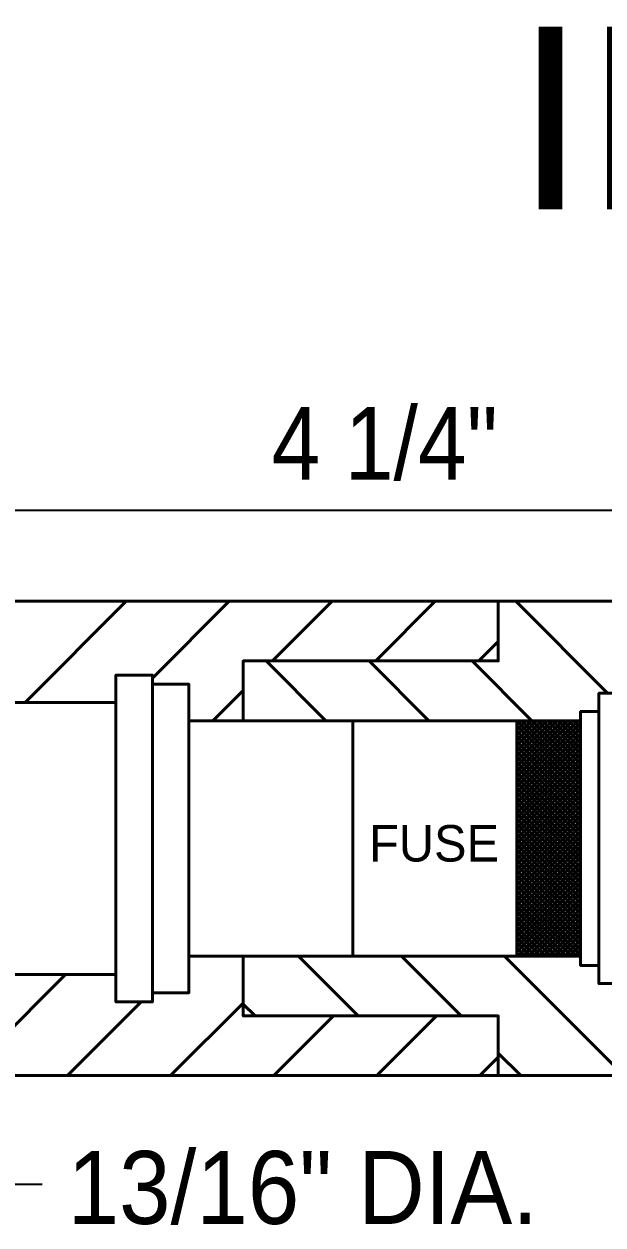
# Model space of a CAD drawing. Extents: x -1 to 679, y 0 to 440.
# Drawn here: x 505.14 to 521.03, y 230.48 to 263.39 of the extents above; entities that cross this region are included whole.
import ezdxf
from ezdxf.enums import TextEntityAlignment as Align

# ---------------------------------------------------------------- set-up
doc = ezdxf.new("R2010")
doc.units = 0
doc.header["$LTSCALE"] = 0.8
doc.layers.add('1', color=7, linetype='Continuous', lineweight=53)

msp = doc.modelspace()

# ---------------------------------------------------------------- linework, layer by layer
at = {"layer": '1', "lineweight": 35}
for p, q in [((484.1543, 250.0712), (546.1543, 250.0712)), ((504.6435, 231.5923), (505.6424, 231.5923))]:
    msp.add_line(p, q, dxfattribs=at)
at = {"layer": '1'}
for p, q in [((505.1687, 244.7994), (507.9405, 247.5712)), ((508.6637, 245.4659), (510.769, 247.5712)), ((511.9615, 245.9353), (513.5974, 247.5712)), ((514.7899, 245.9353), (516.4258, 247.5712)), ((521.1549, 245.0494), (518.6331, 247.5712)), ((517.6183, 245.9353), (518.1543, 246.4713)), ((513.4196, 244.2994), (511.7837, 245.9353)), ((516.248, 244.2994), (514.6121, 245.9353)), ((519.0764, 244.2994), (517.4405, 245.9353)), ((508.6637, 245.2994), (508.6637, 236.8431)), ((510.3256, 244.2994), (511.1543, 245.1282)), ((507.6637, 244.7994), (507.6637, 237.3431)), ((509.6637, 244.2994), (509.6637, 237.8431)), ((518.6637, 244.2994), (511.1543, 244.2994)), ((514.1637, 244.2994), (514.1637, 237.8431)), ((518.6637, 244.1823), (518.7808, 244.2994)), ((518.6637, 244.0409), (518.9222, 244.2994)), ((518.6637, 243.8995), (519.0636, 244.2994)), ((518.6637, 243.7581), (519.205, 244.2994)), ((518.6637, 243.6167), (519.3464, 244.2994)), ((518.6637, 243.4752), (519.4878, 244.2994)), ((518.6637, 243.3338), (519.6292, 244.2994)), ((518.6637, 243.1923), (519.7708, 244.2994)), ((518.6637, 243.0509), (519.9122, 244.2994)), ((518.6637, 242.9095), (520.0536, 244.2994)), ((518.6637, 242.7681), (520.195, 244.2994)), ((518.6637, 242.6267), (520.3364, 244.2994)), ((520.4137, 242.5478), (518.6637, 244.2978)), ((518.6637, 242.4852), (520.4137, 244.2352)), ((520.4137, 242.6892), (518.8035, 244.2994)), ((520.4137, 242.8307), (518.9449, 244.2994)), ((520.4137, 242.9721), (519.0863, 244.2994)), ((520.4137, 243.1135), (519.2278, 244.2994)), ((520.4137, 243.255), (519.3692, 244.2994)), ((520.4137, 243.3964), (519.5107, 244.2994)), ((520.4137, 243.5378), (519.6521, 244.2994)), ((520.4137, 243.6792), (519.7935, 244.2994)), ((520.4137, 243.8207), (519.9349, 244.2994)), ((520.4137, 243.9621), (520.0763, 244.2994)), ((520.4137, 244.1035), (520.2178, 244.2994)), ((520.4137, 244.2449), (520.3592, 244.2994)), ((520.9137, 244.5494), (520.9137, 237.5931)), ((520.4137, 242.4064), (518.6637, 244.1564)), ((518.6637, 242.3438), (520.4137, 244.0938)), ((520.4137, 242.265), (518.6637, 244.015)), ((518.6637, 242.2024), (520.4137, 243.9524)), ((520.4137, 242.1236), (518.6637, 243.8736)), ((518.6637, 242.061), (520.4137, 243.811)), ((520.4137, 241.9822), (518.6637, 243.7322)), ((518.6637, 241.9196), (520.4137, 243.6696)), ((520.4137, 241.8407), (518.6637, 243.5907)), ((518.6637, 241.7782), (520.4137, 243.5282)), ((520.4137, 241.6993), (518.6637, 243.4493)), ((518.6637, 241.6367), (520.4137, 243.3867)), ((520.4137, 241.5579), (518.6637, 243.3079)), ((518.6637, 241.4953), (520.4137, 243.2453)), ((520.4137, 241.4165), (518.6637, 243.1665)), ((518.6637, 241.3539), (520.4137, 243.1039)), ((520.4137, 241.2751), (518.6637, 243.0251)), ((518.6637, 241.2125), (520.4137, 242.9625)), ((520.4137, 241.1337), (518.6637, 242.8837)), ((518.6637, 241.0711), (520.4137, 242.8211)), ((520.4137, 240.9922), (518.6637, 242.7422)), ((518.6637, 240.9297), (520.4137, 242.6797)), ((520.4137, 240.8508), (518.6637, 242.6008)), ((518.6637, 240.7883), (520.4137, 242.5383)), ((520.4137, 240.7094), (518.6637, 242.4594)), ((518.6637, 240.6467), (520.4137, 242.3967)), ((520.4137, 240.5679), (518.6637, 242.3179)), ((518.6637, 240.5053), (520.4137, 242.2553)), ((520.4137, 240.4265), (518.6637, 242.1765)), ((518.6637, 240.3639), (520.4137, 242.1139)), ((520.4137, 240.2851), (518.6637, 242.0351)), ((518.6637, 240.2225), (520.4137, 241.9725)), ((520.4137, 240.1437), (518.6637, 241.8937)), ((518.6637, 240.0811), (520.4137, 241.8311)), ((520.4137, 240.0023), (518.6637, 241.7523)), ((518.6637, 239.9397), (520.4137, 241.6897)), ((520.4137, 239.8608), (518.6637, 241.6108)), ((518.6637, 239.7982), (520.4137, 241.5482)), ((520.4137, 239.7194), (518.6637, 241.4694)), ((518.6637, 239.6568), (520.4137, 241.4068)), ((520.4137, 239.578), (518.6637, 241.328)), ((518.6637, 239.5154), (520.4137, 241.2654)), ((520.4137, 239.4366), (518.6637, 241.1866)), ((518.6637, 239.374), (520.4137, 241.124)), ((520.4137, 239.2952), (518.6637, 241.0452)), ((518.6637, 239.2326), (520.4137, 240.9826)), ((520.4137, 239.1538), (518.6637, 240.9038)), ((518.6637, 239.0912), (520.4137, 240.8412)), ((520.4137, 239.0123), (518.6637, 240.7623)), ((518.6637, 238.9497), (520.4137, 240.6997)), ((520.4137, 238.8709), (518.6637, 240.6209)), ((518.6637, 238.8083), (520.4137, 240.5583)), ((520.4137, 238.7295), (518.6637, 240.4795)), ((518.6637, 238.6669), (520.4137, 240.4169)), ((520.4137, 238.5881), (518.6637, 240.3381)), ((518.6637, 238.5255), (520.4137, 240.2755)), ((520.4137, 238.4467), (518.6637, 240.1967)), ((518.6637, 238.3841), (520.4137, 240.1341)), ((520.4137, 238.3053), (518.6637, 240.0553)), ((518.6637, 238.2427), (520.4137, 239.9927)), ((520.4137, 238.1638), (518.6637, 239.9138)), ((518.6637, 238.1012), (520.4137, 239.8512)), ((520.4137, 238.0223), (518.6637, 239.7723)), ((518.6637, 237.9597), (520.4137, 239.7097)), ((520.4137, 237.8809), (518.6637, 239.6309)), ((520.3101, 237.8431), (518.6637, 239.4895)), ((520.1687, 237.8431), (518.6637, 239.3481)), ((518.6884, 237.8431), (520.4137, 239.5683)), ((518.8298, 237.8431), (520.4137, 239.4269)), ((520.0272, 237.8431), (518.6637, 239.2067)), ((519.8858, 237.8431), (518.6637, 239.0652)), ((518.9712, 237.8431), (520.4137, 239.2855)), ((519.1127, 237.8431), (520.4137, 239.1441)), ((519.2541, 237.8431), (520.4137, 239.0027)), ((519.7444, 237.8431), (518.6637, 238.9238)), ((519.603, 237.8431), (518.6637, 238.7824)), ((519.4616, 237.8431), (518.6637, 238.641)), ((519.3955, 237.8431), (520.4137, 238.8612)), ((519.5369, 237.8431), (520.4137, 238.7198)), ((519.3202, 237.8431), (518.6637, 238.4996)), ((519.1788, 237.8431), (518.6637, 238.3582)), ((519.6783, 237.8431), (520.4137, 238.5784)), ((519.8197, 237.8431), (520.4137, 238.437)), ((519.0373, 237.8431), (518.6637, 238.2167)), ((518.8959, 237.8431), (518.6637, 238.0753)), ((519.9612, 237.8431), (520.4137, 238.2956)), ((520.1026, 237.8431), (520.4137, 238.1542)), ((520.244, 237.8431), (520.4137, 238.0127)), ((514.3081, 236.2072), (512.6722, 237.8431)), ((517.1365, 236.2072), (515.5006, 237.8431)), ((521.6008, 234.5712), (518.329, 237.8431)), ((518.7545, 237.8431), (518.6637, 237.9339)), ((520.3854, 237.8431), (520.4137, 237.8713)), ((503.5079, 234.5712), (506.2797, 237.3431)), ((506.3363, 234.5712), (508.3582, 236.5931)), ((509.1647, 234.5712), (511.1543, 236.5608)), ((511.4796, 236.2072), (511.1543, 236.5324)), ((511.9932, 234.5712), (513.6291, 236.2072)), ((514.8217, 234.5712), (516.4576, 236.2072)), ((517.6501, 234.5712), (518.1543, 235.0755)), ((518.7724, 234.5712), (518.1543, 235.1893))]:
    msp.add_line(p, q, dxfattribs=at)
for points in [[(484.1543, 242.5712), (484.1543, 245.0712), (492.1543, 245.0712), (498.1543, 246.8212), (498.1543, 247.5712), (518.1543, 247.5712), (518.1543, 245.9353), (511.1543, 245.9353), (511.1543, 244.2994), (509.6637, 244.2994), (509.6637, 245.2994), (508.6637, 245.2994), (508.6637, 245.5494), (507.6637, 245.5494), (507.6637, 244.7994), (504.1637, 244.7994), (503.4783, 244.0712)], [(511.1543, 244.2994), (511.1543, 245.9353), (518.1543, 245.9353), (518.1543, 247.5712), (532.1543, 247.5712), (532.1543, 246.8212), (538.1543, 245.0712), (546.1543, 245.0712), (546.1543, 242.5712)], [(525.9137, 244.2994), (521.9137, 244.2994), (521.9137, 245.0494), (520.9137, 245.0494), (520.9137, 244.5494), (520.4137, 244.5494), (520.4137, 244.2994)], [(546.1543, 239.5712), (546.1543, 237.0712), (538.1543, 237.0712), (532.1543, 235.3212), (532.1543, 234.5712), (518.1543, 234.5712), (518.1543, 236.2072), (511.1543, 236.2072)], [(503.4783, 238.0712), (504.1637, 237.3431), (507.6637, 237.3431), (507.6637, 236.5931), (508.6637, 236.5931), (508.6637, 236.8431), (509.6637, 236.8431), (509.6637, 237.8431), (511.1543, 237.8431), (511.1543, 236.2072), (518.1543, 236.2072), (518.1543, 234.5712), (498.1543, 234.5712), (498.1543, 235.3212), (492.1543, 237.0712), (484.1543, 237.0712)], [(511.1543, 236.2072), (511.1543, 237.8431), (518.6637, 237.8431)], [(520.4137, 237.8431), (520.4137, 237.5931), (520.9137, 237.5931), (520.9137, 237.0931), (521.9137, 237.0931), (521.9137, 237.8431), (525.9137, 237.8431)]]:
    msp.add_lwpolyline(points, dxfattribs=at)
msp.add_lwpolyline([(518.6637, 237.8431), (518.6637, 244.2994), (520.4137, 244.2994), (520.4137, 237.8431)], close=True, dxfattribs=at)

# ---------------------------------------------------------------- texts
at = {"layer": '1', "width": 1.05}
msp.add_text('INSTALLATION', height=5, dxfattribs=at).set_placement((543.5785, 258.319), align=Align.CENTER)
at = {"layer": '1'}
for s, width, p in [('4 1/4"', 0.9, (511.9338, 250.9013)), ('13/16" DIA.', 0.95, (506.3365, 230.5062))]:
    msp.add_text(s, height=2, dxfattribs=dict(at, width=width)).set_placement(p)
msp.add_text('FUSE', height=1, dxfattribs=at).set_placement((514.6084, 240.4392))

doc.saveas('drawing.dxf')
